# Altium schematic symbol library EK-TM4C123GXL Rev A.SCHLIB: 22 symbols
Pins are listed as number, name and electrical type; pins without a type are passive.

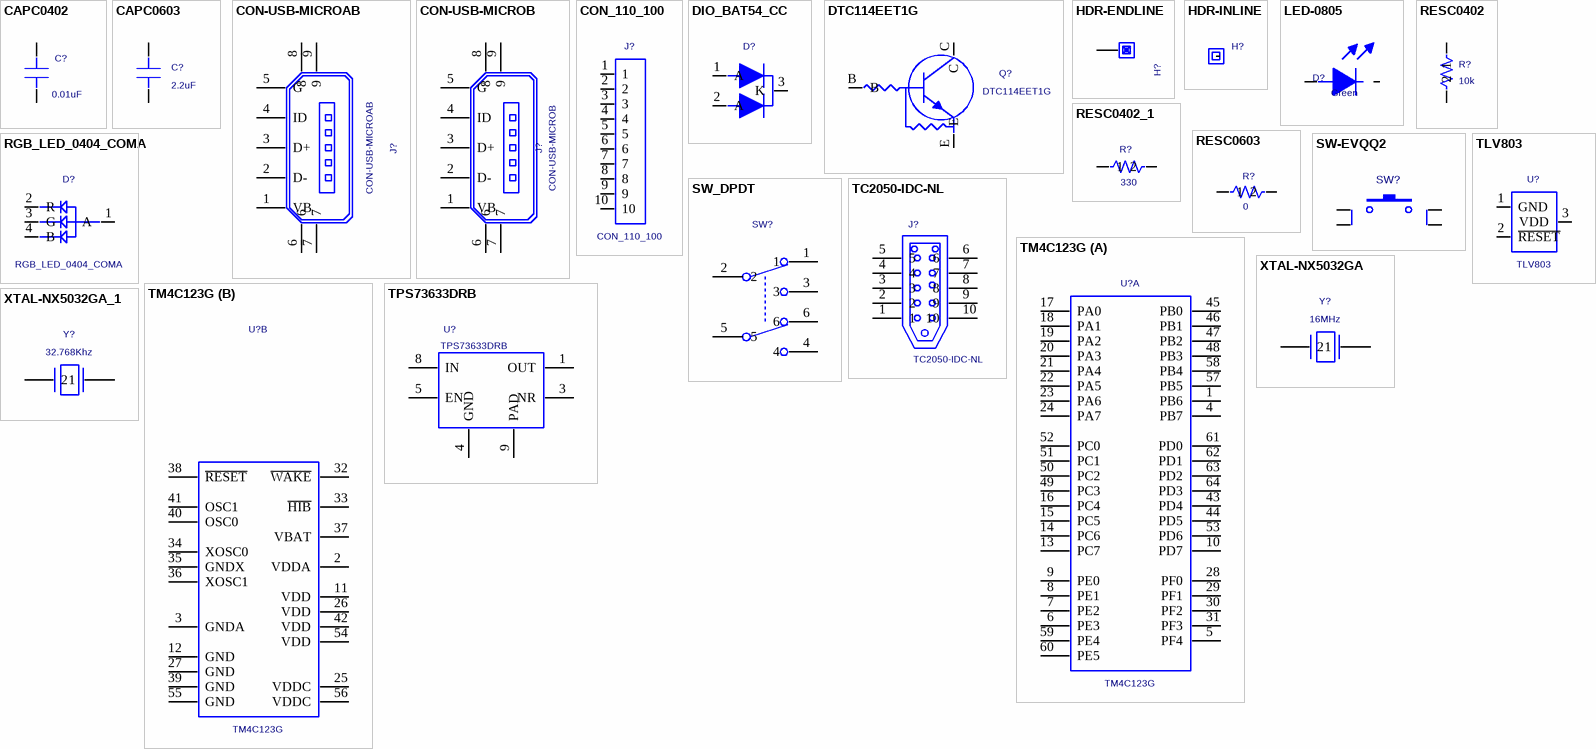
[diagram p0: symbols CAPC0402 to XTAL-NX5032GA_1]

## CAPC0402
designator C?  value 0.01uF  (hidden comment: CAPC0402)
SURFACE MOUNT CAPACITOR 0402; Manufacturer #1: IPC SM-782 STD.; Sim.Analog.Order: Model$; PCB DECAL: CAPC0402N; GNUM: G10-C0402-C103-BBA
footprint CAPC0402N
pins: 1, 2

## CAPC0603
designator C?  value 2.2uF  (hidden comment: CAPC0603)
SURFACE MOUNT CAPACITOR 0.031 X 0.061 INCHES; Manufacturer #1: IPC SM-782 STD.; Sim.Analog.Order: Model$; PCB DECAL: CAPC0603N; GNUM: G10-C0603-C225-HBB
footprint CAPC0603N
pins: 1, 2

## CON-USB-MICROAB
designator J?
Connector, USB micro AB Receptacle SMT; Part Number: ZX62-AB-5PA; Manufacturer #1: Hirose; PCB DECAL: CON-USB-MICRO-S; GNUM: G20-USBU-SMAB-AAA
footprint CON-USB-MICRO-S
pins: 1 VB, 2 D-, 3 D+, 4 ID, 5 G, 6, 7, 8, 9

## CON-USB-MICROB
designator J?
Connector, USB micro AB Receptacle SMT; Part Number: ZX62-B-5PA; Manufacturer #1: Hirose; PCB DECAL: CON-USB-MICRO-S; GNUM: G20-USBM-SMMB-AAA
footprint CON-USB-MICRO-S
pins: 1 VB, 2 D-, 3 D+, 4 ID, 5 G, 6, 7, 8, 9

## CON_110_100
designator J?
PCB DECAL: TSW-110-100; PIN1_X: 0.3; PIN1_Y: 1.4; Geometry.Height: 50.00mil; GNUM: G22-THSTK-2X10-BAC
footprint TSW-110-100
pins: 1, 2, 3, 4, 5, 6, 7, 8, 9, 10

## DIO_BAT54_CC
designator D?  (value not drawn)
PCB DECAL: SC70-3; GNUM: G14-SC700-BAS7-BAA; POPOP: OMIT
footprint SC70-3
pins: 1 A, 2 A, 3 K

## DTC114EET1G
designator Q?
GENERAL PURPOSE NPN SILICON TRANSISTOR; Manufacturer #1: Diodes Inc; PCB DECAL: SC-75/SOT-416; GNUM: G52-SC700-NPNB-AAA
footprint SC-75/SOT-416
pins: B, C, E

## HDR-ENDLINE
designator H?
PCB DECAL: PAD70H39; POPOP: OMIT; Comment_1: HDR-ENDLINE
footprint PAD70H39
pins: 1

## HDR-INLINE
designator H?
POPOP: OMIT; Comment_1: HDR-INLINE
pins: 1

## LED-0805
designator D?  value Green  (hidden comment: LED-0805)
SMT LED IN 0805 PACK; Manufacturer #1: LITE-ON; Part Number: LTST-C170xKT; PCB DECAL: DIOC0805N; GNUM: G14-D0805-GR00-AAA
footprint DIOC0805N
pins: 1, 2

## RESC0402
designator R?  value 10k  (hidden comment: RESC0402)
Resistor,Chip;1.00mm L X 0.5mm W X 0.35mm H; Manufacturer #1: Generic; Part Number: TBD; Also Known As: 0402; PCBL.Component: CHP;RESC;1500;1700;150;400;700;950;600; PCBL.Process: F;N;50;50;200;100;200;250;350;-50;0; Tolerance: 5%; PCB DECAL: RESC0402N; GNUM: G11-R0402-1002-AAA
footprint RESC0402N
pins: 1, 2

## RESC0402_1
designator R?, comment value 330  (hidden comment: RESC0402)
Resistor,Chip;1.00mm L X 0.5mm W X 0.35mm H; Manufacturer #1: Generic; Part Number: TBD; Also Known As: 0402; PCBL.Component: CHP;RESC;1500;1700;150;400;700;950;600; PCBL.Process: F;N;50;50;200;100;200;250;350;-50;0; Tolerance: 5%; PCB DECAL: RESC0402N; GNUM: G11-R0402-3300-AAA; POPOP: OMIT
footprint RESC0402N
pins: 1, 2

## RESC0603
designator R?  value 0  (hidden comment: RESC0603)
PCB DECAL: RESC0603N; GNUM: G11-R0603-R000-AAA
footprint RESC0603N
pins: 1, 2

## RGB_LED_0404_COMA
designator D?
PCB DECAL: 0404_QUAD; GNUM: G14-D0404-RGB3-AAA
footprint 0404_QUAD
pins: 1 A, 2 R, 3 G, 4 B

## SW-EVQQ2
designator SW?  (value not drawn)
Switch, Tact 6mm SMT, 50gf; Manufacturer #1: Panasonic; Part Number: EVQ-Q2B02W; GNUM: G21-4P6MM-B3S1-AAA
footprint SW-EVQQ2
pins: 1, 2, 3, 4

## SW_DPDT
designator SW?  (value not drawn)
PCB DECAL: SW_JS202011SCQN; Geometry.Height: 50.00mil; GNUM: G21-SMGUL-DPDT-AAA
footprint SW_JS202011SCQN
pins: 1, 2, 3, 4, 5, 6

## TC2050-IDC-NL
designator J?
POPOP: OMIT
footprint TC2050-IDC-NL
pins: 1, 2, 3, 4, 5, 6, 7, 8, 9, 10

## TLV803
designator U?
PCB DECAL: SOT23; GNUM: G57-TIDBV-803M-AAA; POPOP: OMIT
footprint SOT23
pins: 1 GND, 2 ~{RESET}, 3 VDD

## TM4C123G
designator U?
PCB DECAL: QFP50P1200X1200X160-64N; GNUM: G50-QFP64-F120-EGC
footprint QFP50P1200X1200X160-64N
part A pins: 1 PB6, 4 PB7, 5 PF4, 6 PE3, 7 PE2, 8 PE1, 9 PE0, 10 PD7, 13 PC7, 14 PC6, 15 PC5, 16 PC4, 17 PA0, 18 PA1, 19 PA2, 20 PA3, 21 PA4, 22 PA5, 23 PA6, 24 PA7, 28 PF0, 29 PF1, 30 PF2, 31 PF3, 43 PD4, 44 PD5, 45 PB0, 46 PB1, 47 PB2, 48 PB3, 49 PC3, 50 PC2, 51 PC1, 52 PC0, 53 PD6, 57 PB5, 58 PB4 (power), 59 PE4, 60 PE5, 61 PD0, 62 PD1, 63 PD2, 64 PD3
part B pins: 2 VDDA (power), 3 GNDA (power), 11 VDD (power), 12 GND (power), 25 VDDC (power), 26 VDD (power), 27 GND (power), 32 ~{WAKE}, 33 ~{HIB}, 34 XOSC0, 35 GNDX (power), 36 XOSC1, 37 VBAT (power), 38 ~{RESET}, 39 GND (power), 40 OSC0, 41 OSC1, 42 VDD (power), 54 VDD (power), 55 GND (power), 56 VDDC

## TPS73633DRB
designator U?
PCB DECAL: TI-DRB-SON8; GNUM: G51-SON08-T633-AAA
footprint TI-DRB-SON8
pins: 1 OUT, 3 NR, 4 GND, 5 EN, 8 IN, 9 PAD

## XTAL-NX5032GA
designator Y?  value 16MHz  (hidden comment: XTAL-NX5032GA)
Crystal, 16.00MHz 5.0x3.2mm SMT; Manufacturer #1: tbd; Part Number: NX5032GA-16.000000MHZ; GNUM: G15-5X3P2-1606-AAA
footprint XTAL-NX5032GA
pins: 1, 2

## XTAL-NX5032GA_1
designator Y?, comment value 32.768Khz  (hidden comment: XTAL-NX5032GA)
PCB DECAL: XTAL-AB26TR; GNUM: G15-AB26T-3272-AAA; P/N: AB26TR
footprint XTAL-AB26TR
pins: 1, 2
